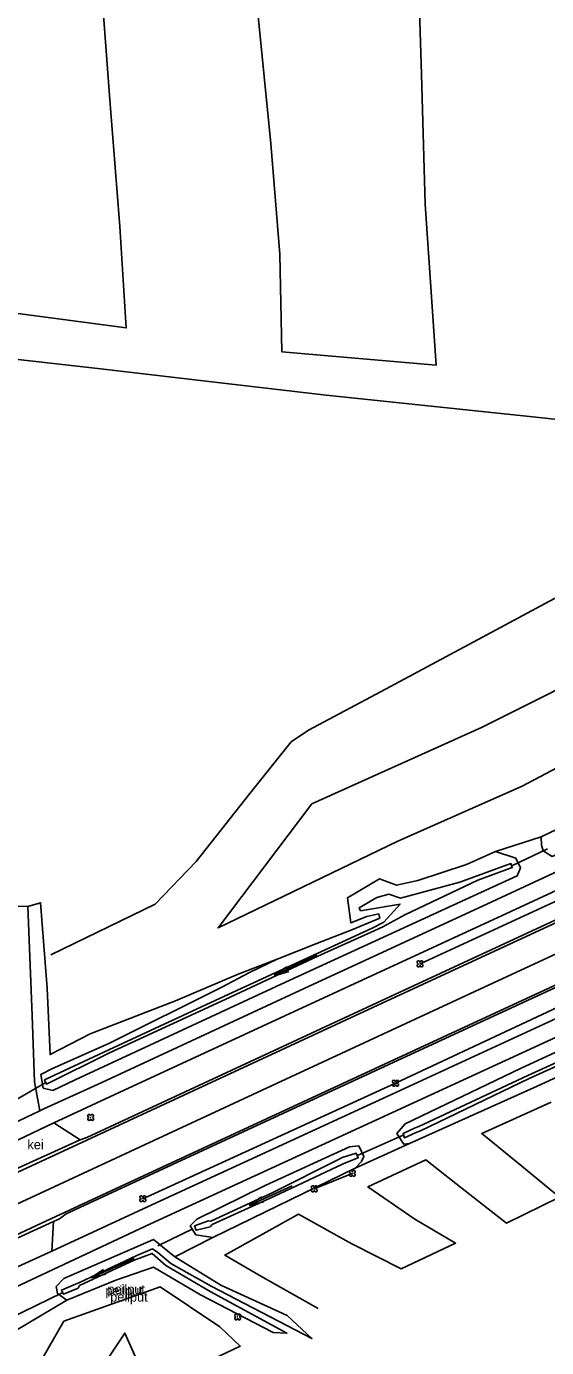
# Model space of a CAD drawing. Extents: x 154825 to 158680, y 370717 to 378075.
# Drawn here: x 157480 to 157534.8, y 372710.3 to 372849.4 of the extents above; entities that cross this region are included whole.
import ezdxf

# ---------------------------------------------------------------- set-up
doc = ezdxf.new("R2010")
doc.units = 0
for name, color, linetype in [('boom', 7, 'Continuous'), ('bos(vs)', 7, 'Continuous'), ('cultuurscheiding', 7, 'Continuous'), ('deelstreep(3-9)', 7, 'Continuous'), ('duiker lijn', 7, 'Continuous'), ('hoogteverschillijn', 7, 'Continuous'), ('insteek sloot', 7, 'Continuous'), ('kantstreep', 7, 'Continuous'), ('keiverharding(vs)', 7, 'Continuous'), ('maaiveldlijn algemeen - gesloten verharding', 7, 'Continuous'), ('maaiveldlijn algemeen - onverhard', 7, 'Continuous'), ('maaiveldlijn algemeen - open verharding', 7, 'Continuous'), ('peilput', 7, 'Continuous'), ('raster - hek', 7, 'Continuous'), ('raster_hekw+inst', 7, 'Continuous'), ('Sloot bodem', 7, 'Continuous'), ('stroomrichting  watergangen', 7, 'Continuous'), ('vlak_Grasland', 7, 'Continuous'), ('vlak_Grazige_vegetatie', 7, 'Continuous')]:
    doc.layers.add(name, color=color, linetype=linetype)

msp = doc.modelspace()

# ---------------------------------------------------------------- linework, layer by layer
at = {"layer": 'boom'}
for points in [[(157521.51, 372750.71), (157562.61, 372769.66)], [(157492.3, 372725.97), (157518.92, 372738.14), (157546.52, 372751.07), (157573.82, 372763.45)], [(157510.36, 372727.01), (157514.37, 372728.64)]]:
    msp.add_lwpolyline(points, dxfattribs=at)
for centre in [(157521.51, 372750.71), (157518.92, 372738.14), (157486.8, 372734.53), (157514.37, 372728.64), (157510.36, 372727.01), (157492.3, 372725.97), (157502.29, 372713.53)]:
    msp.add_circle(centre, 0.006, dxfattribs=at)
for centre, start, end in [((157521.35, 372750.87), 357.075, 272.925), ((157521.35, 372750.55), 87.075, 2.925), ((157521.66, 372750.87), 267.075, 182.925), ((157521.66, 372750.55), 177.075, 92.925), ((157518.76, 372738.29), 357.075, 272.925), ((157518.76, 372737.98), 87.075, 2.925), ((157519.08, 372738.29), 267.075, 182.925), ((157519.08, 372737.98), 177.075, 92.925), ((157486.64, 372734.69), 357.075, 272.925), ((157486.64, 372734.37), 87.075, 2.925), ((157486.95, 372734.69), 267.075, 182.925), ((157486.95, 372734.37), 177.075, 92.925), ((157514.22, 372728.8), 357.075, 272.925), ((157514.22, 372728.48), 87.075, 2.925), ((157514.53, 372728.8), 267.075, 182.925), ((157514.53, 372728.48), 177.075, 92.925), ((157510.2, 372727.17), 357.075, 272.925), ((157510.2, 372726.85), 87.075, 2.925), ((157510.52, 372727.17), 267.075, 182.925), ((157510.52, 372726.85), 177.075, 92.925), ((157492.14, 372726.12), 357.075, 272.925), ((157492.14, 372725.81), 87.075, 2.925), ((157492.46, 372726.12), 267.075, 182.925), ((157492.46, 372725.81), 177.075, 92.925), ((157502.13, 372713.68), 357.075, 272.925), ((157502.13, 372713.37), 87.075, 2.925), ((157502.45, 372713.68), 267.075, 182.925), ((157502.45, 372713.37), 177.075, 92.925)]:
    msp.add_arc(centre, 0.158, start, end, dxfattribs=at)
at = {"layer": 'bos(vs)'}
msp.add_lwpolyline([(157481.52, 372757.13), (157482.23, 372748.13), (157482.53, 372741.14), (157486.75, 372743.33), (157495.74, 372746.81), (157502.33, 372749.63), (157506.46, 372751.18)], dxfattribs=at)
at = {"layer": 'cultuurscheiding'}
for points in [[(157529.47, 372762.55), (157534.28, 372764.07)], [(157476.26, 372757.11), (157477.23, 372756.78), (157480.18, 372756.75), (157481.52, 372757.13)], [(157478.72, 372711.98), (157484.27, 372715.27)]]:
    msp.add_lwpolyline(points, dxfattribs=at)
at = {"layer": 'deelstreep(3-9)'}
msp.add_lwpolyline([(157693.04, 372824.71), (157671.19, 372814.57), (157649.3, 372804.41), (157627.44, 372794.27), (157604.56, 372783.62), (157594.54, 372778.92), (157572.69, 372768.8), (157551.11, 372758.81), (157529.26, 372748.71), (157507.38, 372738.56), (157474.53, 372723.31), (157452.88, 372713.29), (157431.04, 372703.17), (157418.74, 372697.46), (157398.09, 372687.91), (157373.81, 372676.65), (157351.94, 372666.54), (157329.99, 372656.33)], dxfattribs=at)
at = {"layer": 'duiker lijn'}
for points in [[(157534.94, 372762.8), (157531.19, 372761.04)], [(157482, 372738.18), (157476.16, 372734.79)], [(157519.72, 372732.67), (157514.98, 372730.54)], [(157497.58, 372722.78), (157493.86, 372720.99)], [(157478.33, 372713.38), (157483.81, 372716.07)]]:
    msp.add_lwpolyline(points, dxfattribs=at)
at = {"layer": 'hoogteverschillijn'}
for points in [[(157504.38, 372851.2), (157505.78, 372837.11), (157506.74, 372825.44), (157506.96, 372815.16), (157523.22, 372813.77), (157522.05, 372830.72), (157521.66, 372844.37), (157521.14, 372861.35)], [(157475.64, 372819.64), (157490.55, 372817.68), (157489.86, 372828.36), (157488.82, 372841.7), (157487.98, 372853.02)], [(157589.42, 372849.87), (157581.27, 372847.62), (157572.62, 372845.55), (157567.06, 372844.07), (157560.48, 372842.33), (157557.26, 372841.41), (157555.53, 372835.04), (157553.46, 372827.09), (157551.67, 372820.05), (157549.9, 372813.51), (157548.22, 372806.9), (157543.85, 372807.19), (157532.06, 372808.44), (157511.61, 372810.6), (157499.58, 372812), (157487.55, 372813.4), (157478.54, 372814.42)], [(157482.61, 372751.67), (157493.61, 372756.98), (157497.91, 372761.49), (157503.56, 372768.63), (157507.92, 372774.08), (157509.77, 372775.31), (157517.41, 372779.37), (157528.08, 372785.12), (157538.48, 372790.7)], [(157543.19, 372783.22), (157527.98, 372775.61), (157510.12, 372767.56), (157500.22, 372754.48), (157519.16, 372763.63), (157532.26, 372769.42), (157543.45, 372775.3)], [(157510.77, 372714.39), (157504.96, 372717.66), (157500.92, 372720.03), (157508.7, 372724.34), (157514.33, 372721.2), (157519.53, 372718.57), (157525.25, 372721.3), (157520.96, 372723.83), (157516.02, 372727.22), (157522.12, 372730.07), (157525.95, 372727.06), (157530.63, 372723.4), (157536.2, 372726.12), (157532.24, 372729.4), (157528.02, 372732.84), (157535.33, 372736.14)], [(157474.82, 372696.91), (157478.12, 372702.31), (157481.41, 372708.61), (157483.98, 372713.07), (157494.11, 372716.68), (157500.41, 372712.47), (157502.57, 372710.44), (157493.04, 372705.91), (157490.41, 372711.81), (157483.72, 372701.76)]]:
    msp.add_lwpolyline(points, dxfattribs=at)
at = {"layer": 'insteek sloot'}
for points in [[(157534.28, 372764.07), (157534.32, 372763.19), (157534.48, 372762.61), (157535.44, 372762.02), (157543.64, 372765.67), (157560.19, 372772.98), (157571.71, 372778.47), (157586.11, 372785.22), (157589.77, 372786.92), (157589.76, 372787.92), (157588.81, 372788.72)], [(157571.84, 372755.39), (157578.61, 372758.78), (157589.68, 372764.11), (157601.38, 372769.6), (157614.82, 372775.87), (157622.71, 372779.94), (157622.64, 372780.37), (157622.33, 372781.07), (157621.86, 372781.19), (157615.4, 372778.13), (157599.8, 372770.9), (157588.4, 372765.82), (157577.32, 372760.62), (157547.77, 372746.91), (157532.11, 372739.67), (157519.94, 372733.85), (157519.07, 372732.84), (157519.81, 372731.7), (157520.41, 372731.79)], [(157538.52, 372766.1), (157534.28, 372764.07)], [(157506.46, 372751.18), (157503.52, 372749.79), (157500.62, 372748.24), (157488.71, 372742.32), (157482.77, 372739.67), (157481.55, 372739.06), (157481.8, 372737.62), (157482.82, 372737.35), (157485.15, 372738.5), (157507.32, 372748.79), (157526.31, 372757.48), (157531.75, 372759.98), (157532.09, 372760.83), (157531.6, 372761.83), (157529.47, 372762.55)], [(157529.47, 372762.55), (157526.39, 372761.15), (157521.28, 372759.47), (157519.02, 372758.98), (157517.22, 372759.65), (157513.86, 372757.67), (157514.21, 372755.03), (157515.89, 372755.69), (157517.15, 372755.96), (157517.27, 372755.52), (157514.31, 372754.29), (157510.53, 372752.81), (157506.46, 372751.18)], [(157514.66, 372729.18), (157515.33, 372729.88), (157515.58, 372730.41), (157515.05, 372731.54), (157514.09, 372731.42), (157505.18, 372727.36), (157498, 372723.82), (157497.27, 372723.12), (157497.87, 372722.18), (157499.68, 372721.9)], [(157495.66, 372719.84), (157493.42, 372721.68), (157483.96, 372717.57), (157483.17, 372716.71), (157483.31, 372715.97), (157484.27, 372715.27)], [(157484.27, 372715.27), (157489.45, 372717.4), (157493.43, 372718.75), (157498.38, 372715.84), (157506.03, 372711.88)]]:
    msp.add_lwpolyline(points, dxfattribs=at)
at = {"layer": 'kantstreep'}
for points in [[(157810.64, 372876.05), (157801.79, 372871.94), (157775.86, 372859.77), (157754.32, 372849.16), (157753.47, 372848.81), (157743.28, 372844.03), (157725.96, 372836.42), (157713.52, 372830.91), (157693.18, 372821.51), (157668.95, 372810.3), (157650.14, 372801.55), (157633.01, 372793.59), (157612.56, 372784.08), (157591.65, 372774.31), (157568.57, 372763.65), (157543.05, 372751.84), (157518.22, 372740.35), (157495.3, 372729.73), (157482.15, 372723.63), (157473.39, 372719.56)], [(157758.12, 372858.41), (157746.58, 372853.32), (157739.86, 372850.21), (157734.79, 372847.6), (157723.69, 372842.09), (157702.45, 372832.35), (157680.99, 372822.41), (157659.83, 372812.62), (157637.52, 372802.23), (157632.78, 372800), (157617.21, 372792.78), (157595.92, 372782.87), (157569.75, 372770.75), (157543.55, 372758.61), (157517.06, 372746.36), (157486.41, 372732.15), (157469.86, 372724.47), (157454.4, 372717.29), (157430.13, 372706.05), (157404.83, 372694.32), (157376.21, 372681.02), (157354.77, 372671.07), (157328.63, 372658.97)]]:
    msp.add_lwpolyline(points, dxfattribs=at)
at = {"layer": 'maaiveldlijn algemeen - gesloten verharding'}
for points in [[(157485.69, 372732.18), (157486.38, 372732.42), (157516.97, 372746.59), (157543.47, 372758.88), (157569.58, 372771.01), (157595.75, 372783.12), (157617.89, 372793.48), (157648.67, 372807.88)], [(157615.98, 372797.53), (157607.82, 372793.75), (157586.67, 372784), (157571.86, 372777.1), (157549.28, 372766.6), (157528.62, 372757.04), (157508.83, 372747.91), (157487.97, 372738.21), (157481.87, 372735.42), (157481.43, 372735.21)], [(157616.62, 372795.93), (157608.39, 372792.07), (157587.39, 372782.35), (157572.47, 372775.39), (157549.79, 372764.89), (157529.62, 372755.56), (157509.63, 372746.32), (157489.35, 372736.93), (157482.93, 372733.97)], [(157615.77, 372779.93), (157598.27, 372771.87), (157576.77, 372761.96), (157546.39, 372747.82), (157518.61, 372735.04), (157493.11, 372723.32), (157477.74, 372716.13)], [(157482.89, 372723.57), (157483.53, 372723.86), (157484.22, 372724.37), (157495.42, 372729.57), (157518.21, 372740.11), (157543.1, 372751.59), (157568.72, 372763.46), (157597.92, 372776.72)], [(157598.9, 372774.17), (157576.48, 372763.8), (157545.96, 372749.6), (157518.11, 372736.77), (157492.8, 372725.1), (157482.72, 372720.44)], [(157322.19, 372661.35), (157327.37, 372663.76), (157349.88, 372674.18), (157373.63, 372685.15), (157396.47, 372695.77), (157419.84, 372706.62), (157443.82, 372717.77), (157465.99, 372728.1), (157472.46, 372731.05), (157478.48, 372733.83), (157481.43, 372735.21)], [(157479.08, 372732.14), (157482.93, 372733.97)], [(157478.02, 372728.7), (157485.69, 372732.18)], [(157346.42, 372660.21), (157347.63, 372660.98), (157367.07, 372670), (157399.55, 372685.09), (157429.71, 372699.06), (157447.58, 372707.42), (157473.7, 372719.52), (157474.67, 372719.81), (157482.89, 372723.57)], [(157482.72, 372720.44), (157477.53, 372718.1)]]:
    msp.add_lwpolyline(points, dxfattribs=at)
at = {"layer": 'maaiveldlijn algemeen - onverhard'}
msp.add_lwpolyline([(157480.18, 372756.75), (157480.65, 372745.25), (157480.89, 372738.28), (157481.43, 372735.21)], dxfattribs=at)
at = {"layer": 'maaiveldlijn algemeen - open verharding'}
for points in [[(157482.93, 372733.97), (157485.69, 372732.18)], [(157482.72, 372720.44), (157482.89, 372723.57)]]:
    msp.add_lwpolyline(points, dxfattribs=at)
at = {"layer": 'raster - hek'}
for points in [[(157514.66, 372729.18), (157520.41, 372731.79)], [(157495.66, 372719.84), (157499.68, 372721.9)]]:
    msp.add_lwpolyline(points, dxfattribs=at)
at = {"layer": 'raster_hekw+inst'}
for points in [[(157571.84, 372755.39), (157561.01, 372750.32), (157551.28, 372745.8), (157533.45, 372737.66), (157520.41, 372731.79)], [(157514.66, 372729.18), (157499.68, 372721.9)], [(157495.66, 372719.84), (157500.51, 372716.85), (157507.49, 372713.68)]]:
    msp.add_lwpolyline(points, dxfattribs=at)
at = {"layer": 'Sloot bodem'}
for points in [[(157516.48, 372754.47), (157517.69, 372755.1), (157519.4, 372756.99), (157515.25, 372756.3), (157515.1, 372756.62), (157516.94, 372757.68), (157518.23, 372758.03), (157519.46, 372757.63), (157525.71, 372759.32), (157531.09, 372761.27), (157531.22, 372760.85), (157527.6, 372759.53), (157519.89, 372755.87), (157517.59, 372754.61), (157516.35, 372754.03), (157510.75, 372751.51), (157500.96, 372746.96), (157488.79, 372741.33), (157482.14, 372738.04), (157481.94, 372738.48), (157488.7, 372741.65), (157500.91, 372747.31), (157510.67, 372751.78), (157516.48, 372754.47)], [(157550.38, 372746.91), (157532.85, 372738.95), (157521.37, 372733.57), (157520.99, 372733.42), (157519.73, 372732.82), (157519.87, 372732.37), (157521.18, 372732.99), (157521.55, 372733.11), (157533, 372738.64), (157550.49, 372746.53)], [(157514.99, 372730.29), (157514.77, 372730.77), (157513.29, 372730.31), (157512.98, 372730.13), (157505.93, 372726.6), (157499.46, 372723.62), (157499.21, 372723.64), (157497.75, 372723.1), (157497.93, 372722.65), (157499.39, 372723.02), (157499.61, 372723.24), (157506.09, 372726.21), (157513.39, 372729.65), (157513.66, 372729.76), (157514.99, 372730.29)], [(157507.48, 372711.82), (157499.38, 372716.2), (157494.71, 372718.93), (157493.27, 372720.2), (157491.38, 372719.48), (157485.63, 372716.82), (157485.47, 372716.55), (157483.94, 372715.91), (157483.71, 372716.33), (157485.2, 372716.96), (157485.54, 372717.12), (157491.66, 372719.99), (157493.31, 372720.69), (157493.86, 372720.29), (157495.25, 372719.16), (157499.5, 372716.75), (157510.11, 372711.23)]]:
    msp.add_lwpolyline(points, dxfattribs=at)
at = {"layer": 'stroomrichting  watergangen'}
for p, q in [((157510.63, 372751.66), (157506.15, 372749.46)), ((157506.15, 372749.46), (157507.43, 372750.39)), ((157506.17, 372749.45), (157507.69, 372749.89)), ((157508.04, 372727.31), (157503.49, 372725.26)), ((157503.49, 372725.26), (157504.79, 372726.15)), ((157503.51, 372725.25), (157505.04, 372725.64)), ((157491.38, 372719.68), (157486.83, 372717.63)), ((157486.83, 372717.63), (157488.14, 372718.52)), ((157486.85, 372717.62), (157488.38, 372718.01))]:
    msp.add_line(p, q, dxfattribs=at)
at = {"layer": 'vlak_Grasland'}
msp.add_lwpolyline([(157538.52, 372766.1), (157534.28, 372764.07), (157529.47, 372762.55), (157526.39, 372761.15), (157521.28, 372759.47), (157519.02, 372758.98), (157517.22, 372759.65), (157513.86, 372757.67), (157514.21, 372755.03), (157515.89, 372755.69), (157517.15, 372755.96), (157517.27, 372755.52), (157514.31, 372754.29), (157510.53, 372752.81), (157506.46, 372751.18), (157502.33, 372749.63), (157495.74, 372746.81), (157486.75, 372743.33), (157482.53, 372741.14), (157482.23, 372748.13), (157481.52, 372757.13), (157480.18, 372756.75), (157477.23, 372756.78)], dxfattribs=at)
at = {"layer": 'vlak_Grazige_vegetatie'}
for points in [[(157619.31, 372796.8), (157617.89, 372793.48), (157595.75, 372783.12), (157569.58, 372771.01), (157543.47, 372758.88), (157516.97, 372746.59), (157486.38, 372732.42), (157485.69, 372732.18), (157482.93, 372733.97), (157489.35, 372736.93), (157509.63, 372746.32), (157529.62, 372755.56), (157549.79, 372764.89), (157572.47, 372775.39), (157587.39, 372782.35), (157608.39, 372792.07), (157616.62, 372795.93), (157616.7, 372795.78)], [(157588.81, 372788.72), (157589.76, 372787.92), (157589.77, 372786.92), (157586.11, 372785.22), (157571.71, 372778.47), (157560.19, 372772.98), (157543.64, 372765.67), (157535.44, 372762.02), (157534.48, 372762.61), (157534.32, 372763.19), (157534.28, 372764.07), (157538.52, 372766.1), (157542.71, 372767.63), (157559.6, 372775.27), (157568.99, 372779.97), (157585.87, 372787.4)], [(157622.33, 372781.07), (157622.64, 372780.37), (157622.71, 372779.94), (157614.82, 372775.87), (157601.38, 372769.6), (157589.68, 372764.11), (157578.61, 372758.78), (157571.84, 372755.39), (157561.01, 372750.32), (157551.28, 372745.8), (157533.45, 372737.66), (157520.41, 372731.79), (157519.81, 372731.7), (157519.07, 372732.84), (157519.94, 372733.85), (157532.11, 372739.67), (157547.77, 372746.91), (157577.32, 372760.62), (157588.4, 372765.82), (157599.8, 372770.9), (157615.4, 372778.13), (157621.86, 372781.19)], [(157519.73, 372732.82), (157519.87, 372732.37), (157521.18, 372732.99), (157521.55, 372733.11), (157533, 372738.64), (157550.49, 372746.53), (157560.4, 372751.17), (157578.09, 372759.53), (157588.5, 372764.5), (157600.67, 372769.89), (157605.86, 372772.51), (157615.43, 372777), (157622.38, 372780.14), (157622.25, 372780.39), (157615.32, 372777.33), (157605.76, 372772.87), (157600.53, 372770.32), (157588.38, 372764.9), (157577.97, 372759.95), (157560.27, 372751.61), (157550.38, 372746.91), (157532.85, 372738.95), (157521.37, 372733.57), (157520.99, 372733.42)], [(157492.8, 372725.1), (157482.72, 372720.44), (157482.89, 372723.57), (157483.53, 372723.86), (157484.22, 372724.37), (157495.42, 372729.57), (157518.21, 372740.11), (157543.1, 372751.59), (157568.72, 372763.46), (157591.83, 372773.94), (157594.36, 372772.07), (157576.48, 372763.8), (157545.96, 372749.6), (157518.11, 372736.77)], [(157531.6, 372761.83), (157532.09, 372760.83), (157531.75, 372759.98), (157526.31, 372757.48), (157507.32, 372748.79), (157485.15, 372738.5), (157482.82, 372737.35), (157481.8, 372737.62), (157481.55, 372739.06), (157482.77, 372739.67), (157488.71, 372742.32), (157500.62, 372748.24), (157503.52, 372749.79), (157506.46, 372751.18), (157510.53, 372752.81), (157514.31, 372754.29), (157517.27, 372755.52), (157517.15, 372755.96), (157515.89, 372755.69), (157514.21, 372755.03), (157513.86, 372757.67), (157517.22, 372759.65), (157519.02, 372758.98), (157521.28, 372759.47), (157526.39, 372761.15), (157529.47, 372762.55)], [(157525.71, 372759.32), (157519.46, 372757.63), (157518.23, 372758.03), (157516.94, 372757.68), (157515.1, 372756.62), (157515.25, 372756.3), (157519.4, 372756.99), (157517.69, 372755.1), (157516.48, 372754.47), (157510.67, 372751.78), (157500.91, 372747.31), (157488.7, 372741.65), (157481.94, 372738.48), (157482.14, 372738.04), (157488.79, 372741.33), (157500.96, 372746.96), (157510.75, 372751.51), (157516.35, 372754.03), (157517.59, 372754.61), (157519.89, 372755.87), (157527.6, 372759.53), (157531.22, 372760.85), (157531.09, 372761.27)], [(157515.05, 372731.54), (157515.58, 372730.41), (157515.33, 372729.88), (157514.66, 372729.18), (157499.68, 372721.9), (157497.87, 372722.18), (157497.27, 372723.12), (157498, 372723.82), (157505.18, 372727.36), (157514.09, 372731.42)], [(157505.93, 372726.6), (157499.46, 372723.62), (157499.21, 372723.64), (157497.75, 372723.1), (157497.93, 372722.65), (157499.39, 372723.02), (157499.61, 372723.24), (157506.09, 372726.21), (157513.39, 372729.65), (157513.66, 372729.76), (157514.99, 372730.29), (157514.77, 372730.77), (157513.29, 372730.31), (157512.98, 372730.13)], [(157493.42, 372721.68), (157495.66, 372719.84), (157500.51, 372716.85), (157507.49, 372713.68), (157510.11, 372711.23), (157499.5, 372716.75), (157495.25, 372719.16), (157493.86, 372720.29), (157493.31, 372720.69), (157491.66, 372719.99), (157485.54, 372717.12), (157485.2, 372716.96), (157483.71, 372716.33), (157483.94, 372715.91), (157485.47, 372716.55), (157485.63, 372716.82), (157491.38, 372719.48), (157493.27, 372720.2), (157494.71, 372718.93), (157499.38, 372716.2), (157507.48, 372711.82), (157506.03, 372711.88), (157498.38, 372715.84), (157493.43, 372718.75), (157489.45, 372717.4), (157484.27, 372715.27), (157483.31, 372715.97), (157483.17, 372716.71), (157483.96, 372717.57)]]:
    msp.add_lwpolyline(points, close=True, dxfattribs=at)
for points in [[(157549.28, 372766.6), (157528.62, 372757.04), (157508.83, 372747.91), (157487.97, 372738.21), (157481.87, 372735.42), (157481.43, 372735.21), (157480.89, 372738.28), (157480.65, 372745.25), (157480.18, 372756.75), (157481.52, 372757.13), (157482.23, 372748.13), (157482.53, 372741.14), (157486.75, 372743.33), (157495.74, 372746.81), (157502.33, 372749.63), (157506.46, 372751.18), (157503.52, 372749.79), (157500.62, 372748.24), (157488.71, 372742.32), (157482.77, 372739.67), (157481.55, 372739.06), (157481.8, 372737.62), (157482.82, 372737.35), (157485.15, 372738.5), (157507.32, 372748.79), (157526.31, 372757.48), (157531.75, 372759.98), (157532.09, 372760.83), (157531.6, 372761.83), (157529.47, 372762.55), (157534.28, 372764.07), (157534.32, 372763.19), (157534.48, 372762.61), (157535.44, 372762.02)], [(157477.74, 372716.13), (157493.11, 372723.32), (157518.61, 372735.04), (157546.39, 372747.82)], [(157547.77, 372746.91), (157532.11, 372739.67), (157519.94, 372733.85), (157519.07, 372732.84), (157519.81, 372731.7), (157520.41, 372731.79), (157514.66, 372729.18), (157515.33, 372729.88), (157515.58, 372730.41), (157515.05, 372731.54), (157514.09, 372731.42), (157505.18, 372727.36), (157498, 372723.82), (157497.27, 372723.12), (157497.87, 372722.18), (157499.68, 372721.9), (157495.66, 372719.84), (157493.42, 372721.68), (157483.96, 372717.57), (157483.17, 372716.71), (157483.31, 372715.97), (157484.27, 372715.27), (157478.72, 372711.98)]]:
    msp.add_lwpolyline(points, dxfattribs=at)

# ---------------------------------------------------------------- texts
at = {"layer": 'keiverharding(vs)'}
msp.add_text('kei', height=1, dxfattribs=at).set_placement((157480.14, 372731.17))
at = {"layer": 'peilput'}
for p in [(157488.57, 372715.94), (157488.35, 372715.79), (157488.86, 372715.13)]:
    msp.add_text('peilput', height=1, dxfattribs=at).set_placement(p)

doc.saveas('drawing.dxf')
